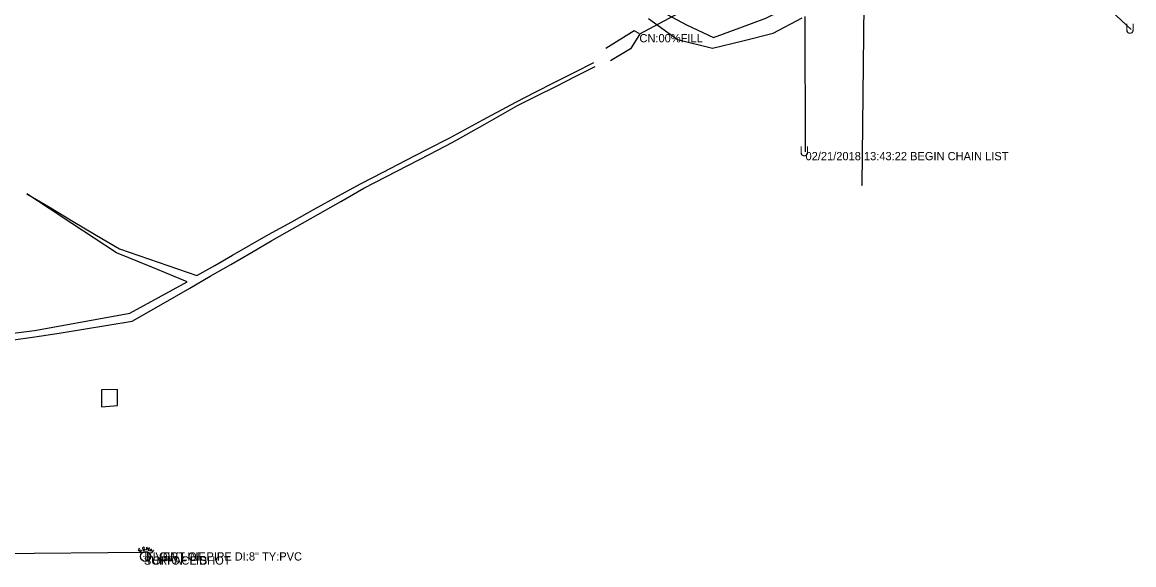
# Model space of a CAD drawing. Extents: x 1707085 to 1720058, y 548761 to 560063.
# Drawn here: x 1711989 to 1712661, y 549044 to 549372 of the extents above; entities that cross this region are included whole.
import ezdxf

# ---------------------------------------------------------------- set-up
doc = ezdxf.new("R2010")
doc.units = 0
for name, color, linetype in [('3', 7, 'Continuous'), ('Default', 7, 'Continuous'), ('R_Water Annot', 7, 'Continuous'), ('S_DRG_PT_SYM', 7, 'Continuous'), ('S_EDGE_CONCRETE', 7, 'Continuous'), ('S_EDGE_PAVEMENT', 7, 'Continuous'), ('S_GRD_PT_SYM', 7, 'Continuous'), ('S_MANHOLE_ANNOT', 7, 'Continuous'), ('S_MISC_TOPO_POINT', 7, 'Continuous'), ('S_PAVEMENT_CROWN', 7, 'Continuous'), ('S_SANITARY_SEWER', 7, 'Continuous'), ('S_SANITARY_SEWER_ANNOT', 7, 'Continuous'), ('S_SIDE_DRAIN_ANNOT', 7, 'Continuous'), ('S_UNDERGROUND_CABLE', 7, 'Continuous'), ('S_UNDERGROUND_CABLE_ANNOT', 7, 'Continuous'), ('S_UTL_PT_SYM', 7, 'Continuous')]:
    doc.layers.add(name, color=color, linetype=linetype)

msp = doc.modelspace()

# ---------------------------------------------------------------- linework, layer by layer
for points in [[(1712361.72, 549365.43), (1712358.65, 549367.05), (1712341.52, 549356.46)], [(1712362.05, 549364.77), (1712356.52, 549356.24), (1712344.43, 549348.85)], [(1711981.83, 549184.05), (1711996.36, 549185.8), (1712010.77, 549188.42), (1712025.17, 549191.04), (1712039.58, 549193.66), (1712053.98, 549196.28), (1712071.27, 549205.84), (1712088.57, 549215.4), (1712067.19, 549224.09), (1712045.81, 549232.78), (1712032.29, 549241.72), (1712018.77, 549250.65), (1712005.25, 549259.58), (1711991.73, 549268.52), (1712005.7, 549260.2), (1712019.66, 549251.88), (1712033.62, 549243.57), (1712047.59, 549235.25), (1712070.96, 549227.16), (1712094.34, 549219.06), (1712105.2, 549225.28), (1712116.07, 549231.51), (1712126.94, 549237.73), (1712137.8, 549243.95), (1712151.78, 549251.67), (1712165.75, 549259.38), (1712179.73, 549267.09), (1712193.7, 549274.8), (1712207.1, 549281.71), (1712220.5, 549288.62), (1712233.9, 549295.52), (1712247.3, 549302.43), (1712267.21, 549313.23), (1712287.13, 549324.04), (1712298.91, 549330.02), (1712310.7, 549336), (1712322.49, 549341.98), (1712334.28, 549347.96)], [(1711982.11, 549180.05), (1711996.52, 549181.97), (1712011.21, 549184.37), (1712025.9, 549186.76), (1712040.58, 549189.15), (1712055.27, 549191.55), (1712072.7, 549201.5), (1712090.12, 549211.46), (1712102.54, 549218.66), (1712114.95, 549225.86), (1712127.36, 549233.07), (1712139.77, 549240.27), (1712153.65, 549248.17), (1712167.52, 549256.07), (1712181.4, 549263.97), (1712195.27, 549271.87), (1712208.62, 549278.77), (1712221.97, 549285.68), (1712235.32, 549292.58), (1712248.67, 549299.48), (1712268.45, 549310.7), (1712288.23, 549321.92), (1712299.96, 549327.81), (1712311.7, 549333.7), (1712323.44, 549339.59), (1712335.18, 549345.48)]]:
    msp.add_lwpolyline(points)
at = {"layer": '3'}
msp.add_line((1712397.33, 549384.07), (1712361.92, 549365.14), dxfattribs=at)
at = {"layer": 'R_Water Annot'}
msp.add_line((1712497.57, 549383.08), (1712496.4, 549273.84), dxfattribs=at)
at = {"layer": 'S_DRG_PT_SYM'}
msp.add_lwpolyline([(1712361.92, 549365.14), (1712361.92, 549365.19), (1712361.92, 549365.14), (1712361.87, 549365.14), (1712361.92, 549365.14), (1712361.92, 549365.09), (1712361.92, 549365.14), (1712361.97, 549365.14)], dxfattribs=at)
at = {"layer": 'S_EDGE_CONCRETE'}
msp.add_lwpolyline([(1712046.49, 549150.12), (1712036.71, 549149.98), (1712036.85, 549139.8), (1712046.56, 549140.56)], close=True, dxfattribs=at)
at = {"layer": 'S_EDGE_PAVEMENT'}
msp.add_lwpolyline([(1712367.29, 549374.48), (1712384.89, 549361.9), (1712406.02, 549356.55), (1712424.38, 549361.08), (1712442.74, 549365.6), (1712460.36, 549375)], dxfattribs=at)
at = {"layer": 'S_GRD_PT_SYM'}
msp.add_lwpolyline([(1712062.41, 549049.31), (1712062.41, 549049.36), (1712062.41, 549049.31), (1712062.36, 549049.31), (1712062.41, 549049.31), (1712062.41, 549049.26), (1712062.41, 549049.31), (1712062.46, 549049.31)], dxfattribs=at)
at = {"layer": 'S_PAVEMENT_CROWN'}
msp.add_lwpolyline([(1712262.08, 549508.97), (1712273.19, 549495.92), (1712284.3, 549482.88), (1712301.14, 549465.86), (1712314.12, 549449.22), (1712327.1, 549432.57), (1712342.27, 549416.46), (1712357.44, 549400.34), (1712365.03, 549390.24), (1712372.63, 549380.14), (1712390.32, 549370.7), (1712406.74, 549363.12), (1712422.56, 549368.89), (1712438.39, 549374.65), (1712455.94, 549383.35), (1712473.5, 549392.05), (1712493.73, 549403.76), (1712513.96, 549415.46), (1712532.63, 549425.37), (1712551.3, 549435.29), (1712569.98, 549445.2), (1712588.65, 549455.12)], dxfattribs=at)
at = {"layer": 'S_SANITARY_SEWER'}
for p, q in [((1712059.09, 549053.61), (1712059.01, 549053.22)), ((1712059.63, 549054), (1712059.09, 549053.61)), ((1712060.06, 549053.92), (1712059.63, 549054)), ((1712066.07, 549052.37), (1712067.31, 549053.84)), ((1711673.3, 549048.29), (1712062.72, 549051.79)), ((1712059.01, 549053.22), (1712059.21, 549052.95)), ((1712059.21, 549052.95), (1712059.63, 549052.83)), ((1712059.63, 549052.83), (1712060.18, 549053.18)), ((1712060.18, 549052.02), (1712059.79, 549052.1)), ((1712060.18, 549053.18), (1712060.64, 549053.1)), ((1712060.72, 549052.41), (1712060.18, 549052.02)), ((1712060.64, 549053.1), (1712060.8, 549052.83)), ((1712060.8, 549052.83), (1712060.72, 549052.41)), ((1712066.72, 549053.14), (1712067.69, 549052.33)), ((1712068.27, 549053.03), (1712067.03, 549051.55))]:
    msp.add_line(p, q, dxfattribs=at)
for points in [[(1712062.73, 549054.54), (1712062.38, 549054.81), (1712061.73, 549054.73), (1712061.49, 549054.38), (1712061.53, 549054.07), (1712061.88, 549053.76), (1712062.5, 549053.88), (1712062.89, 549053.57), (1712062.93, 549053.26), (1712062.66, 549052.87), (1712062.04, 549052.79), (1712061.69, 549053.07)], [(1712065.17, 549052.68), (1712065.72, 549054.54), (1712064.67, 549053.53), (1712064.28, 549054.96), (1712063.74, 549053.1)]]:
    msp.add_lwpolyline(points, dxfattribs=at)
msp.add_circle((1712063.42, 549049.31), 3.05, dxfattribs=at)
at = {"layer": 'S_UNDERGROUND_CABLE'}
for p, q in [((1712659.13, 549367.93), (1712580.62, 549440.92)), ((1712462.29, 549293.82), (1712462.01, 549375.82))]:
    msp.add_line(p, q, dxfattribs=at)
at = {"layer": 'S_UTL_PT_SYM'}
for points in [[(1712496.4, 549273.84), (1712496.4, 549273.89), (1712496.4, 549273.84), (1712496.34, 549273.84), (1712496.4, 549273.84), (1712496.4, 549273.79), (1712496.4, 549273.84), (1712496.45, 549273.84)], [(1712062.72, 549051.79), (1712062.72, 549051.84), (1712062.72, 549051.79), (1712062.67, 549051.79), (1712062.72, 549051.79), (1712062.72, 549051.74), (1712062.72, 549051.79), (1712062.77, 549051.79)], [(1712063.73, 549051.78), (1712063.73, 549051.83), (1712063.73, 549051.78), (1712063.68, 549051.78), (1712063.73, 549051.78), (1712063.73, 549051.73), (1712063.73, 549051.78), (1712063.78, 549051.78)]]:
    msp.add_lwpolyline(points, dxfattribs=at)

# ---------------------------------------------------------------- texts
at = {"layer": 'Default'}
for p in [(1712655.5, 549365.39), (1712458.66, 549291.27)]:
    msp.add_text('U', height=6, rotation=360, dxfattribs=at).set_placement(p)
at = {"layer": 'S_MANHOLE_ANNOT'}
msp.add_text('FLOW LINE', height=5, dxfattribs=at).set_placement((1712063.73, 549046.78))
at = {"layer": 'S_MISC_TOPO_POINT'}
msp.add_text('SURFACE SHOT', height=5, dxfattribs=at).set_placement((1712062.41, 549044.31))
at = {"layer": 'S_SANITARY_SEWER_ANNOT'}
for s, p in [('INVERT OF PIPE DI:8" TY:PVC', (1712062.72, 549046.79)), ('TOP OF LID', (1712063.42, 549044.31))]:
    msp.add_text(s, height=5, dxfattribs=at).set_placement(p)
at = {"layer": 'S_SIDE_DRAIN_ANNOT'}
msp.add_text('CN:00%FILL', height=5, dxfattribs=at).set_placement((1712361.92, 549360.14))
at = {"layer": 'S_UNDERGROUND_CABLE_ANNOT'}
msp.add_text('02/21/2018 13:43:22 BEGIN CHAIN LIST', height=5, dxfattribs=at).set_placement((1712462.29, 549288.82))

doc.saveas('drawing.dxf')
